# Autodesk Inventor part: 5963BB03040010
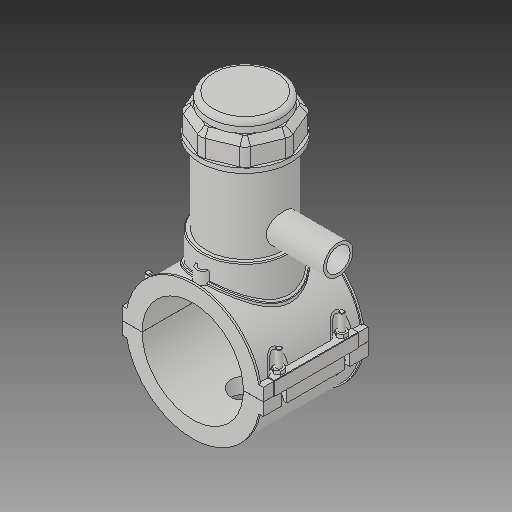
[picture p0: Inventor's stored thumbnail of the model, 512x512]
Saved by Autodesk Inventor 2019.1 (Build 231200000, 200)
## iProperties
Created: 2017-07
Part Number: 5963BB03040010
Material: Generic
Description: PLASSON TAPPING SADDLE 4''IPS x 1''IPS
Document SubType Name: Modeling
Designer: KIM
Mass: 1712.7 g
Surface Area: 2671.49 cm^2
Volume: 1712.7 cm^3
Density: 1 g/cm^3
Appearance: Default
Author: KIM
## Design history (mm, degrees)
derived "5963B.ipt"
feature "Solid1::5963B.ipt"
feature "Solid2::5963B.ipt"
feature "Solid4::5963B.ipt"
feature "Solid5::5963B.ipt"
tag "TaggingFeature1"
body "Solid1"
body "Solid2"
other parameters: "d0" = 114.1, "d2" = 159.004, "d3" = 28.525, "d4" = 118.11, "d5" = 0, "d6" = 0.1, "d8" = 0, "d19" = 6, "d20" = 6, "d21" = 70.866, "d23" = 0, "d24" = 35.433, "d26" = 0, "d29" = 3, "d30" = 38.03333, "d31" = 6, "d32" = 0, "d33" = 0, "d34" = 0.6, "d40" = 77.1316, "d41" = 102.69, "d43" = 0, "d45" = 0, "d47" = 145.031, "d70" = 15, "d72" = 0, "d73" = 6, "d75" = 5, "d76" = 0, "d77" = 5.705, "d78" = 87.05, "d79" = 15, "d80" = 47.244, "d82" = 5 deg, "d84" = 4, "d85" = 14, "d86" = 0, "d87" = 3, "d88" = 0, "d89" = 1, "d90" = 1, "d91" = 94.488, "d92" = 0, "d93" = 0.5, "d94" = 60.05263, "d96" = 151.2966, "d97" = 2.3622, "d98" = 0, "d102" = 1.141, "d120" = 140 deg, "d121" = 24.228, "d122" = 20 deg, "d123" = 296.66, "d124" = 88.998, "d126" = 0, "d143" = 117.523, "d145" = 26.33077, "d149" = 1.7115, "d150" = 28.96385, "d153" = 118.11, "d154" = 0, "d156" = 74.165, "d157" = 160 deg, "d159" = 6.846, "d161" = 1.7115, "d162" = 70.866, "d163" = 0, "d164" = 57.05, "d167" = 11.41, "d168" = 72.3561, "d170" = 3.2805, "d172" = 0, "d173" = 1, "d175" = 57.05, "d176" = 20 deg, "d177" = 7.987, "d178" = 34.23, "d180" = 0, "d183" = 13.692, "d184" = 6.3896, "d185" = 38.38575, "d186" = 38.38575, "d187" = 74.165, "d188" = 10.269, "d189" = 7.987, "d190" = 0, "d191" = 111.2475, "d193" = 6.1236, "d194" = 4.13385, "d195" = 90 deg, "d197" = 0, "d199" = 0, "d200" = 17.115, "d202" = 0, "d203" = 177.038, "d204" = 97.5555, "d205" = 71.883, "d206" = 87.2865, "d207" = 132.7785, "d208" = 138.08964, "d209" = 164.64534, "d210" = 88.3134, "d211" = 102.69, "d212" = 82.152, "d213" = 43.5366, "d216" = 0, "d217" = 11.41, "d218" = 5.705, "d219" = 1.141, "d222" = 114.1, "d224" = 0, "d230" = 6.846, "d233" = 6, "d236" = 79.502, "d237" = 35.433, "d238" = 6.02433, "d240" = 35.433, "d241" = 35.433, "d242" = 35.433, "d243" = 6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
